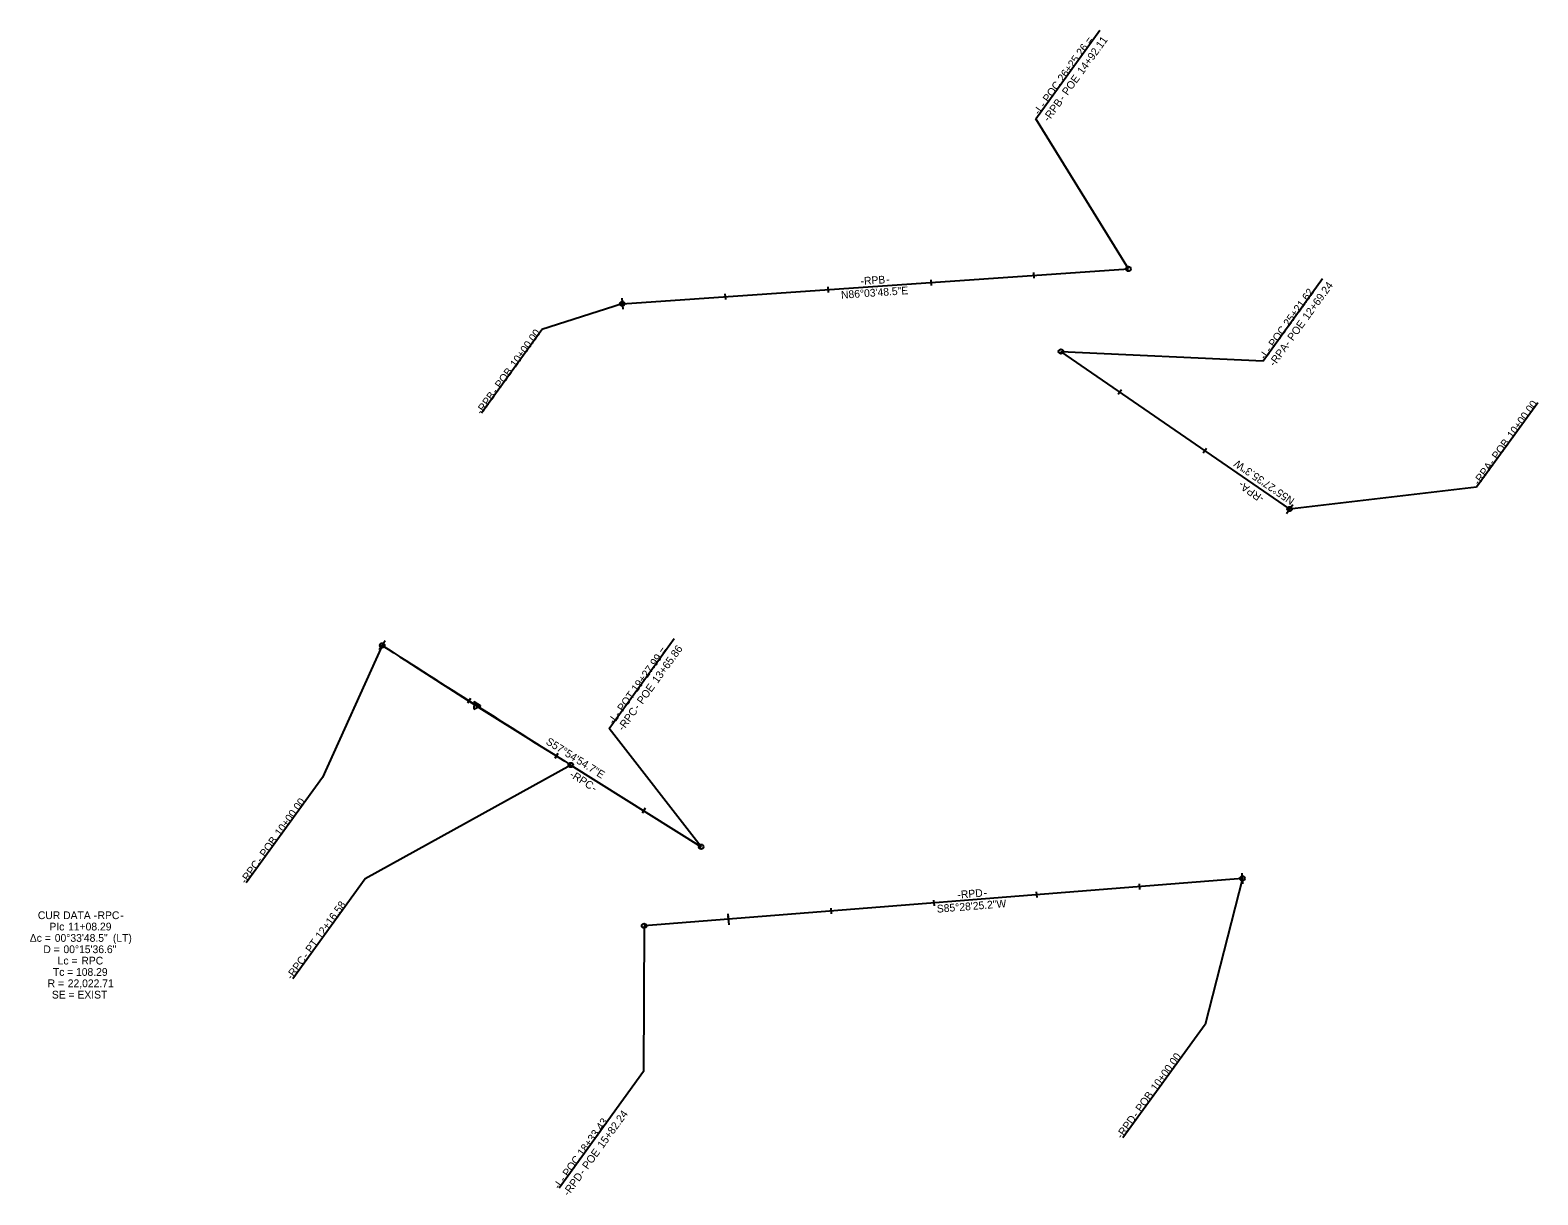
# Model space of a CAD drawing. Extents: x 1183719 to 1185182, y 573494 to 574623.
import ezdxf

# ---------------------------------------------------------------- set-up
doc = ezdxf.new("R2010")
doc.units = 0
for name, color, linetype in [('Default', 7, 'Continuous'), ('P_NCDOT_Vertical_Profile_Ground_Line', 7, 'Continuous'), ('P_RDY_Bridge_Approach_Slab', 7, 'Continuous'), ('P_RDY_Bridge_Rail', 7, 'Continuous'), ('P_RDY_GRAU_CAT1_Cell', 7, 'Continuous'), ('P_RDY_Guardrail', 7, 'Continuous'), ('P_RDY_Road_Guardrail', 7, 'Continuous')]:
    doc.layers.add(name, color=color, linetype=linetype)

msp = doc.modelspace()

# ---------------------------------------------------------------- linework, layer by layer
at = {"layer": 'Default'}
for p, q in [((1184152.1, 573968.4), (1184091.5, 574007.2)), ((1184152.1, 573968.4), (1184213.1, 573930.1)), ((1184152.1, 573968.4), (1184152.1, 573968.4)), ((1184243.8, 573910.9), (1184370.3, 573831.6))]:
    msp.add_line(p, q, dxfattribs=at)
msp.add_lwpolyline([(1184149.9, 573964.9), (1184156.3, 573968.2), (1184150.2, 573972.1)], close=True, dxfattribs=at)
at = {"layer": 'P_NCDOT_Vertical_Profile_Ground_Line'}
for p, q in [((1184293.8, 574358.1), (1184784.8, 574391.9)), ((1184941.1, 574159.1), (1184719.3, 574311.8)), ((1184243.8, 573910.9), (1184370.3, 573831.6)), ((1184895.3, 573800.9), (1184314.9, 573755))]:
    msp.add_line(p, q, dxfattribs=at)
msp.add_arc((1195941.7, 592569.9), 22022.7, 237.35174, 237.91521, dxfattribs=at)
at = {"layer": 'P_RDY_Bridge_Approach_Slab'}
for p, q in [((1184694.8, 574537.2), (1184757.1, 574623.3)), ((1184784.8, 574391.9), (1184694.8, 574537.2)), ((1184915.4, 574302.7), (1184973.1, 574382.4)), ((1184293.8, 574358.1), (1184215.7, 574333)), ((1184157.3, 574252.3), (1184215.7, 574333)), ((1184719.3, 574311.8), (1184915.4, 574302.7)), ((1185122.4, 574180.5), (1185181.8, 574262.5)), ((1184941.1, 574159.1), (1185122.4, 574180.5)), ((1184281, 573946.4), (1184344.1, 574033.5)), ((1184060.9, 574026.8), (1184002.9, 573898.8)), ((1184370.3, 573831.6), (1184281, 573946.4)), ((1184243.8, 573910.9), (1184044.4, 573800.5)), ((1184002.9, 573898.8), (1183929.1, 573796.8)), ((1184044.4, 573800.5), (1183974.2, 573703.5)), ((1184895.3, 573800.9), (1184859, 573659.4)), ((1184314.9, 573755), (1184314.2, 573613.7)), ((1184859, 573659.4), (1184779.3, 573549.3)), ((1184314.2, 573613.7), (1184232.4, 573500.7))]:
    msp.add_line(p, q, dxfattribs=at)
for centre in [(1184784.8, 574391.9), (1184293.8, 574358.1), (1184719.3, 574311.8), (1184941.1, 574159.1), (1184060.9, 574026.8), (1184243.8, 573910.9), (1184370.3, 573831.6), (1184895.3, 573800.9), (1184314.9, 573755)]:
    msp.add_circle(centre, 2.25, dxfattribs=at)
at = {"layer": 'P_RDY_Guardrail'}
for p, q in [((1184293.4, 574363.4), (1184294.2, 574352.8)), ((1184938, 574154.7), (1184944.1, 574163.5)), ((1184063.8, 574031.3), (1184058.1, 574022.4)), ((1184895.7, 573795.6), (1184894.9, 573806.2)), ((1184397.3, 573756.1), (1184396.4, 573766.7))]:
    msp.add_line(p, q, dxfattribs=at)
at = {"layer": 'P_RDY_Road_Guardrail'}
for p, q in [((1184592.9, 574381.4), (1184593.3, 574375.9)), ((1184692.7, 574388.3), (1184693.1, 574382.8)), ((1184393.4, 574367.7), (1184393.8, 574362.2)), ((1184493.1, 574374.6), (1184493.5, 574369.1)), ((1184774.8, 574270.3), (1184777.9, 574274.8)), ((1184857.1, 574213.6), (1184860.3, 574218.1)), ((1184146.7, 573975.4), (1184143.8, 573970.7)), ((1184231.3, 573922), (1184228.3, 573917.3)), ((1184316, 573868.9), (1184313.1, 573864.2)), ((1184795.8, 573790.3), (1184795.4, 573795.8)), ((1184596.5, 573774.5), (1184596, 573780)), ((1184696.1, 573782.4), (1184695.7, 573787.9)), ((1184496.8, 573766.6), (1184496.3, 573772.1)), ((1184397.1, 573758.7), (1184396.6, 573764.2))]:
    msp.add_line(p, q, dxfattribs=at)

# ---------------------------------------------------------------- texts
at = {"layer": 'P_RDY_Bridge_Approach_Slab'}
for s, p in [('-L- POC 26+25.26 =', (1184698.2, 574540.6)), ('14+92.11', (1184740.4, 574579.8)), ('POE', (1184725.7, 574559.5)), ('RPB', (1184709.3, 574536.8)), ('- ', (1184722, 574554.3)), ('-', (1184707.3, 574534)), ('12+69.24', (1184959, 574341.8)), ('-L- POC 25+21.62', (1184917.2, 574303.3)), ('POE', (1184944.3, 574321.5)), ('10+00.00', (1184190.3, 574295.8)), ('- ', (1184940.6, 574316.4)), ('RPA', (1184928.4, 574299.5)), ('POB', (1184175.6, 574275.5)), ('-', (1184926.3, 574296.7)), ('RPB', (1184159.2, 574252.8)), ('- ', (1184171.9, 574270.3)), ('10+00.00', (1185157.3, 574226.8)), ('-', (1184157.2, 574250)), ('POB', (1185142.6, 574206.5)), ('RPA', (1185126.7, 574184.5)), ('- ', (1185138.9, 574201.3)), ('-', (1185124.6, 574181.7)), ('-L- POT 19+27.99 =', (1184285.5, 573949.9)), ('13+65.86', (1184328.1, 573989.5)), ('POE', (1184313.4, 573969.2)), ('RPC', (1184296.7, 573946.1)), ('- ', (1184309.6, 573964)), ('-', (1184294.6, 573943.3)), ('10+00.00', (1183962.1, 573841.3)), ('POB', (1183947.4, 573821)), ('RPC', (1183930.6, 573797.9)), ('- ', (1183943.6, 573815.8)), ('-', (1183928.6, 573795.1)), ('12+16.58', (1184001.5, 573741.4)), ('PT', (1183991.9, 573728.2)), ('RPC', (1183975.2, 573705.1)), ('- ', (1183988.2, 573723)), ('-', (1183973.2, 573702.2)), ('10+00.00', (1184811.7, 573594.2)), ('POB', (1184797, 573573.9)), ('15+82.24', (1184275, 573538.6)), ('-L- POC 18+33.43', (1184232.4, 573499)), ('RPD', (1184780.3, 573550.8)), ('- ', (1184793.3, 573568.7)), ('-', (1184778.3, 573547.9)), ('POE', (1184260.3, 573518.3)), ('- ', (1184256.6, 573513.1)), ('RPD', (1184243.6, 573495.2)), ('-', (1184241.6, 573492.4))]:
    msp.add_text(s, height=7.5, rotation=54.103, dxfattribs=at).set_placement(p)
at = {"layer": 'P_RDY_Bridge_Rail'}
for s, p in [('CUR DATA -', (1183726.9, 573761.5)), ('RPC', (1183784.8, 573761.5)), ('-', (1183806.9, 573761.5)), ('PIc ', (1183738.1, 573750.5)), ('11+08.29', (1183756.2, 573750.5)), ('Δc = ', (1183719.1, 573739.5)), ('D = ', (1183732.2, 573728.5)), ('00°33\'48.5"', (1183743.3, 573739.5)), ('00°15\'36.6"', (1183751.7, 573728.5)), (' (LT)', (1183796.9, 573739.5)), ('Lc = ', (1183746.1, 573717.5)), ('RPC', (1183769.1, 573717.5)), ('Tc = ', (1183741.5, 573706.5)), ('108.29', (1183763.9, 573706.5)), ('R = ', (1183736.4, 573695.5)), ('SE = EXIST', (1183740.5, 573684.5)), ('22,022.71', (1183755.9, 573695.5))]:
    msp.add_text(s, height=7.5, dxfattribs=at).set_placement(p)
at = {"layer": 'P_RDY_GRAU_CAT1_Cell'}
for s, rotation, p in [('-', 3.9365, (1184525.1, 574376.3)), ('RPB', 3.9365, (1184528.5, 574376.5)), ('-', 3.9365, (1184550, 574378)), ('N86°03\'48.5"E', 3.9365, (1184506.2, 574362.9)), ('N55°27\'35.3"W', 145.4598, (1184946.5, 574168.7)), ('-', 145.4598, (1184897.2, 574184.6)), ('RPA', 145.4598, (1184914.3, 574172.8)), ('-', 145.4598, (1184917.2, 574170.8)), ('S57°54\'54.7"E', 327.9152, (1184219, 573931.7)), ('-', 327.9152, (1184241.9, 573899.8)), ('RPC', 327.9152, (1184244.9, 573898)), ('-', 327.9152, (1184263.6, 573886.2)), ('S85°28\'25.2"W', 4.5263, (1184599.2, 573767.7)), ('-', 4.5263, (1184619, 573781.3)), ('RPD', 4.5263, (1184622.5, 573781.6)), ('-', 4.5263, (1184644.5, 573783.3))]:
    msp.add_text(s, height=7.5, rotation=rotation, dxfattribs=at).set_placement(p)

doc.saveas('drawing.dxf')
